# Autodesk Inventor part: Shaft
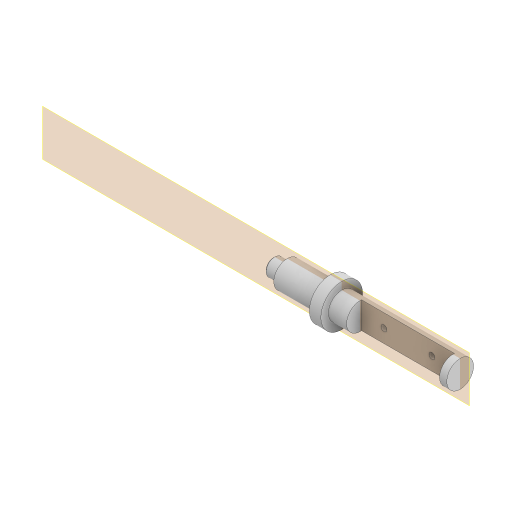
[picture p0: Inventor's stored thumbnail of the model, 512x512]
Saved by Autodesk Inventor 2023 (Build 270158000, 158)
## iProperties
Created: 2019-03
Part Number: Shaft
Material: Generic
Document SubType Name: Modeling
Designer: LENOVO-CADCIM
Density: 1 g/cm^3
Appearance: Default
Author: LENOVO-CADCIM
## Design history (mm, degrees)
sketch "Sketch1"
  geometry: L1 (284.311, 0)-(1023.188, 0); L2 (391.676, 0)-(391.676, -18); L3 (391.676, -18)-(420.576, -18); L4 (420.576, -18)-(420.576, -28); L5 (420.576, -28)-(510.376, -28); L6 (510.376, -28)-(510.376, -43.6); L7 (510.376, -43.6)-(534.376, -43.6); L8 (534.376, -43.6)-(534.376, -28); L9 (534.376, -28)-(781.476, -28); L10 (781.476, -28)-(781.476, 0); L11 (391.676, 0)-(781.476, 0); 1 further point
  constraints: 22 end point, 8 perpendicular, 5 point on line, 1 collinear, 1 horizontal
  dimensions: "d0" = 28.9 distance of L2.end L3.end; "d1" = 89.8 distance of L4.end L5.end; "d2" = 24 distance of L6.end L7.end; "d3" = 247.1 distance of L8.end L9.end; "d4" = 56 diameter of L9 L1; "d5" = 87.2 diameter of L7 L1; "d6" = 36 diameter of L3 L1
revolve "Revolution1" sketch "Sketch1" stored, may be unused: angle "d7" = 90 deg
sketch "Sketch4"
  geometry: L1 (-781.476, 28)-(-534.376, 28) reference; L2 (-572.576, 28)-(-766.376, 28); L3 (-766.376, 28)-(-766.376, -3.1); L4 (-766.376, -3.1)-(-572.576, -3.1); L5 (-572.576, -3.1)-(-572.576, 28); L6 (-781.476, -28)-(-534.376, -28) reference; 2 further points
  constraints: 8 end point, 2 parallel, 1 horizontal, 1 perpendicular, 1 point on line
  dimensions: "d16" = 24.9 distance between parallel lines of L6 L4; "d17" = 15.1 distance from line of L1.start L3; "d40" = 193.8 distance of L3.end L4.end
extrude "Extrusion3" cut sketch "Sketch4" stored distance "d18" = 257; taper "d19" = 0 deg
sketch "Sketch6"
  geometry: L1 (-180.9, 45.828)-(-180.9, 9.828) reference; L2 (-180.9, 27.828)-(320.546, 27.828); L3 (0, 55.828)-(0, -0.172) reference; 5 further points
  constraints: 2 end point, 2 point on line, 1 horizontal, 1 midpoint
  dimensions: "d24" = 100 distance of point (46.9, 27.828) point (146.9, 27.828); "d25" = 46.9 distance from line of L3 point (46.9, 27.828)
hole "Hole1" sketch "Sketch6" at (46.9, 27.828), (146.9, 27.828) diameter "d26" = 12.5; stored, may be unused: countersink angle "d30" = 90 deg, drill point angle "d32" = 118 deg; dims "d27" = 6, "d28" = 100, "d29" = 25, "d31" = 310
chamfer "Chamfer1" distance "d33" = 3; stored, may be unused: second distance "d34" = 2, angle "d35" = 45 deg
sketch "Sketch7"
  geometry: L1 (8, -22)-(-8, -22); L2 (-8, -22)-(-8, -26.833); L3 (8, -26.833)-(8, -22); L4 (0, 0)-(0, 64); C1 r 28 at (0, 0) reference; A1 r 28 centre (0, 0) between (-8, -26.833) and (8, -26.833); A2 r 28 centre (0, 0) between (8, -26.833) and (-8, -26.833) reference; 4 further points
  constraints: 8 end point, 3 point on circle, 1 centre point, 1 coincident, 1 concentric, 1 horizontal, 1 parallel, 1 perpendicular, 1 vertical, 1 other
  dimensions: "d36" = 16 distance between parallel lines of L3 L2; "d37" = 50 distance from line of point (0, 28) L1
extrude "Extrusion5" cut sketch "Sketch7" distance "d38" = 62.5; taper "d39" = 0 deg
body "Solid1"
